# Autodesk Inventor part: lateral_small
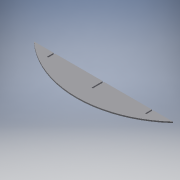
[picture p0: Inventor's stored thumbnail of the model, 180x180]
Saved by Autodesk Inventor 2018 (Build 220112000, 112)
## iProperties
Created: 2019-03
Part Number: lateral_small
Material: Generic
Document SubType Name: Modeling
Designer: vpimentel
Density: 1 g/cm^3
Appearance: Default
Author: vpimentel
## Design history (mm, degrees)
extrude "Extrusion1" new body sketch "Sketch1" distance "d2" = 2.9 (= d1); taper "d3" = 0 deg
body "Solid1"
other parameters: "d1" = 2.9 (derived)
